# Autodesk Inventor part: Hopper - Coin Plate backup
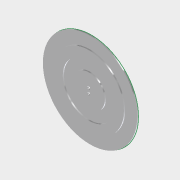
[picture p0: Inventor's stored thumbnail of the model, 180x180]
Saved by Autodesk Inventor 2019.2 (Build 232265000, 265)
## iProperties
Created: 2005-11
Part Number: Hopper - Coin Plate backup
Document SubType Name: Modeling
Designer: floress
Material: Aluminum 6061
Density: 2.7 g/cm^3
Appearance: Aluminum - Flat
Mass: 36.8496 g
Surface Area: 227.957 cm^2
Volume: 13.648 cm^3
Author: floress
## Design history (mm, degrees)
sketch "Sketch1"
  geometry: C1 r 44.45 at (0, 0); C2 r 1.778 at (0, -3.175); C3 r 1.778 at (0, 3.175); 1 further point
  constraints: 3 centre point, 1 coincident, 1 equal radius
  dimensions: "d0" = 88.9 diameter of C1; "d1" = 3.556 diameter of C2
extrude "Extrusion1" new body sketch "Sketch1" distance "d2" = 1.5875; taper "d3" = 0 deg
sketch "Sketch2"
  geometry: C1 r 59.531 at (0, 0); C2 r 6.35 at (0, 0) reference
  constraints: 1 centre point
  dimensions: "d16" = 119.0625 diameter of C1
extrude "Extrusion2" join sketch "Sketch2" distance "d5" = 1.5875; taper "d6" = 0 deg
sketch "Sketch4"
  geometry: C1 r 1.778 at (0, 3.175) reference; C2 r 1.778 at (0, -3.175) reference; C3 r 44.45 at (0, 0) reference; C4 r 32.873 at (0, 0); C5 r 20.173 at (0, 0); 1 further point
  constraints: 2 centre point
  dimensions: "d17" = 12.7 radial gap between concentric circles of C4 C5
extrude "Extrusion4" cut sketch "Sketch4" distance "d18" = 1.5875; taper "d19" = 0 deg
sketch "Sketch5"
  geometry: C1 r 59.531 at (0, 0) reference; C2 r 1.778 at (0, 3.175) reference; C3 r 1.778 at (0, -3.175) reference; 1 further point
sketch "Sketch3"
  geometry: C1 r 0.794 at (0, 53.907); C2 r 0.794 at (-18.437, 50.656); C3 r 0.794 at (-34.651, 41.295); C4 r 0.794 at (-46.685, 26.954); C5 r 0.794 at (-53.088, 9.361); C6 r 0.794 at (-53.088, -9.361); C7 r 0.794 at (-46.685, -26.954); C8 r 0.794 at (-34.651, -41.295); C9 r 0.794 at (-18.437, -50.656); C10 r 0.794 at (0, -53.907); C11 r 0.794 at (18.437, -50.656); C12 r 0.794 at (34.651, -41.295); C13 r 0.794 at (46.685, -26.954); C14 r 0.794 at (53.088, -9.361); C15 r 0.794 at (53.088, 9.361); C16 r 0.794 at (46.685, 26.954); C17 r 0.794 at (34.651, 41.295); C18 r 0.794 at (18.437, 50.656); 2 further points
  constraints: 18 centre point, 1 coincident, 1 vertical alignment, 37 other
  dimensions: "d12" = 360 deg dimension on point (0, 0) C1.centre (derived)
extrude "Extrusion3" join sketch "Sketch3" distance "d14" = 4.7625; taper "d15" = 0 deg
body "Solid1"
node "Reference4"
node "Projected Loop2"
